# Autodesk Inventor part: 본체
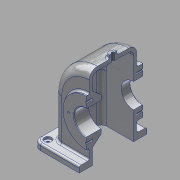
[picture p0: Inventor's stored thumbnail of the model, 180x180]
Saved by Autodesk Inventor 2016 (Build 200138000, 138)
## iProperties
Created: 2018-08
Part Number: 본체
Material: 알루미늄 6061
Document SubType Name: Modeling
Designer: 301-08
Density: 2.7 g/cm^3
Appearance: 알루미늄 - 평지
Mass: 1092.08 g
Surface Area: 1182.21 cm^2
Volume: 404.475 cm^3
Author: 301-08
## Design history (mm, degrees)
sketch "스케치1"
  geometry: L1 (58, 78)-(58, 0); L2 (-58, 78)-(-58, 0); L3 (58, 0)-(-58, 0); A1 r 58 centre (0, 78) between (58, 78) and (-58, 78); 1 further point
  constraints: 6 end point, 2 point on circle, 2 tangent, 2 vertical, 1 centre point, 1 horizontal, 1 midpoint, 1 vertical alignment
  dimensions: "d3" = 58 radius of A1; "d4" = 78 distance from line of L3 A1.centre
extrude "돌출1" new body sketch "스케치1" stored distance "d5" = 77; taper "d6" = 0 deg
sketch "스케치2"
  geometry: L1 (58, 0)-(58, 78) reference; L2 (-58, 78)-(-58, 0) reference; L3 (-52, 0)-(-52, 78); L4 (52, 78)-(52, 0); L5 (52, 0)-(-52, 0); A1 r 58 centre (0, 78) between (58, 78) and (-58, 78) reference; A2 r 52 centre (0, 78) between (52, 78) and (-52, 78); 1 further point
  constraints: 6 end point, 2 point on circle, 2 point on line, 1 centre point, 1 midpoint, 1 perpendicular, 2 other
  dimensions: "d7" = 6 radial gap between concentric circles of A1 A2
extrude "돌출2" cut sketch "스케치2" stored distance "d8" = 67; taper "d9" = 0 deg
sketch "스케치3"
  geometry: L1 (-90.651, 65)-(98.401, 65); C1 r 38 at (0, 65); 1 further point
  constraints: 2 end point, 1 centre point, 1 horizontal, 1 point on line, 1 vertical alignment
  dimensions: "d10" = 65 distance from line of point (0, 0) L1; "d11" = 76 diameter of C1
extrude "돌출3" join sketch "스케치3" distance "d12" = 5; taper "d13" = 0 deg
sketch "스케치4"
  geometry: L1 (81.18, -65)-(-117.972, -65); L2 (58, 0)-(-58, 0) reference; C1 r 38 at (0, -65); 2 further points
  constraints: 2 end point, 1 centre point, 1 horizontal, 1 midpoint, 1 point on line, 1 vertical alignment
  dimensions: "d14" = 65 distance between parallel lines of L2 L1; "d15" = 76 diameter of C1
extrude "돌출4" join sketch "스케치4" distance "d16" = 10; taper "d17" = 0 deg
sketch "스케치5"
  geometry: L1 (-52.99, 65)-(78.307, 65); L2 (33.5, 0)-(-33.5, 0) reference; L3 (-33.5, 130)-(-33.5, 78) reference; L4 (-33.5, 104.747)-(-19.5, 93); L5 (-19.5, 93)-(-19.5, 65); L6 (-33.5, 104.747)-(-33.5, 65); L7 (-33.5, 78)-(-33.5, 0) reference; L8 (-43.5, 103)-(-43.5, 27) reference; 1 further point
  constraints: 8 end point, 4 point on line, 1 horizontal, 1 vertical
  dimensions: "d18" = 65 distance between parallel lines of L2 L1; "d19" = 50 deg angle of L4 L5; "d20" = 56 diameter of L4.end L1; "d21" = 24 distance between parallel lines of L8 L5
revolve "회전1" sketch "스케치5" stored, may be unused: angle "d22" = 90 deg
sketch "스케치6"
  geometry: L1 (133, -93.5)-(-17, -93.5); L2 (-17, -93.5)-(-17, 16.5); L3 (-17, 16.5)-(133, 16.5); L4 (133, 16.5)-(133, -93.5); L5 (133, -93.5)-(-17, 16.5); L6 (-17, -93.5)-(133, 16.5); 1 further point
  constraints: 12 end point, 2 midpoint, 2 parallel, 1 horizontal, 1 perpendicular
  dimensions: "d23" = 150 distance of L2.end L3.end; "d24" = 110 distance of L1.end L2.end
extrude "돌출5" join sketch "스케치6" distance "d25" = 10; taper "d26" = 0 deg
sketch "스케치7"
  geometry: L1 (23, 21.5)-(127, 21.5) reference; L2 (127, 21.5)-(127, 88.5) reference; L3 (23, 88.5)-(23, 21.5) reference; L4 (127, 88.5)-(23, 88.5) reference; L5 (127, 21.5)-(23, 21.5); L6 (23, 21.5)-(127, 21.5) reference; L7 (23, 88.5)-(23, 21.5) reference; L8 (23, 21.5)-(23, 88.5); L9 (127, 21.5)-(127, 88.5); L10 (127, 88.5)-(23, 88.5) reference; L11 (127, 88.5)-(23, 88.5); 1 further point
  constraints: 8 end point, 4 collinear
extrude "돌출6" cut sketch "스케치7" distance "d27" = 10; taper "d28" = 0 deg
sketch "스케치8"
  geometry: L1 (-88.097, 0)-(105.07, 0); C1 r 20 at (0, 0); 1 further point
  constraints: 2 end point, 1 centre point, 1 horizontal, 1 point on line, 1 vertical alignment
  dimensions: "d29" = 65 distance from line of point (0, -65) L1; "d30" = 40 diameter of C1
extrude "돌출7" cut sketch "스케치8" distance "d31" = 24; taper "d32" = 0 deg
sketch "스케치9"
  geometry: L1 (82.709, 0)-(-104.261, 0); L2 (75, 65)-(-75, 65) reference; C1 r 20 at (0, 0); 2 further points
  constraints: 2 end point, 1 centre point, 1 horizontal, 1 midpoint, 1 point on line, 1 vertical alignment
  dimensions: "d33" = 65 distance between parallel lines of L2 L1; "d34" = 40 diameter of C1
extrude "돌출8" cut sketch "스케치9" distance "d35" = 15; taper "d36" = 0 deg
node "작업 평면1"
sketch "스케치10"
  geometry: C1 r 6 at (0, 0); 1 further point
  constraints: 1 centre point, 1 coincident
  dimensions: "d38" = 12 diameter of C1
extrude "돌출9" join sketch "스케치10" stored distance "d39" = 10; taper "d40" = 5 deg
hole "구멍1" diameter "d43" = 4.459; stored, may be unused: countersink angle "d47" = 90 deg, drill point angle "d49" = 118 deg; dims "d41" = 10, "d42" = 10, "d44" = 10, "d45" = 4, "d46" = 2, "d48" = 30.55
fillet "모깎기1" dims "d50" = 12
fillet "모깎기2" dims "d51" = 3
sketch "스케치11"
  geometry: L1 (5, 13.5)-(-121, 13.5) reference; L2 (-130, 4.5)-(-130, -81.5) reference; L3 (-121, -90.5)-(5, -90.5) reference; L4 (14, -81.5)-(14, 4.5) reference; L5 (-116, 0)-(0, 0) reference; L6 (0, 0)-(0, -77) reference; L7 (0, -77)-(-116, -77) reference; L8 (-116, -77)-(-116, 0) reference; L9 (-110, -5)-(-110, -72) reference; L10 (-110, -72)-(-6, -72) reference; L11 (-6, -72)-(-6, -5) reference; L12 (-6, -5)-(-110, -5) reference; A1 r 9 centre (5, 4.5) between (14, 4.5) and (5, 13.5) reference; A2 r 9 centre (-121, 4.5) between (-121, 13.5) and (-130, 4.5) reference; A3 r 9 centre (-121, -81.5) between (-130, -81.5) and (-121, -90.5) reference; A4 r 9 centre (5, -81.5) between (5, -90.5) and (14, -81.5) reference; 5 further points
  constraints: 4 coincident
hole "구멍2" sketch "스케치11" at (-121, 4.5), (-121, -81.5), (5, 4.5), (5, -81.5) diameter "d52" = 5; stored, may be unused: countersink angle "d56" = 90 deg, drill point angle "d58" = 118 deg; dims "d53" = 10, "d54" = 12, "d55" = 4, "d57" = 30.55
fillet "모깎기3" dims "d59" = 13
fillet "모깎기4" dims "d60" = 8
fillet "모깎기5" dims "d61" = 3
fillet "모깎기6" dims "d62" = 3
fillet "모깎기7" dims "d63" = 3
fillet "모깎기8" dims "d64" = 3
sketch "스케치12" dims "d65" = 58
  geometry: C1 r 20 at (0, 0) reference; 3 further points
  constraints: 2 vertical alignment, 1 coincident, 2 other
hole "구멍3" sketch "스케치12" at (0, 29) diameter "d66" = 3.242; stored, may be unused: countersink angle "d70" = 90 deg, drill point angle "d72" = 118 deg; dims "d67" = 8, "d68" = 4, "d69" = 2, "d71" = 10
sketch "스케치13" dims "d76" = 58
  geometry: C1 r 20 at (0, 0) reference; 3 further points
  constraints: 2 vertical alignment, 1 coincident, 2 other
hole "구멍4" sketch "스케치13" at (0, -29) diameter "d77" = 3.242; stored, may be unused: countersink angle "d81" = 90 deg, drill point angle "d83" = 118 deg; dims "d78" = 8, "d79" = 4, "d80" = 2, "d82" = 10
sketch "스케치14"
  geometry: L1 (0, -13)-(65, -13) reference; L2 (78, -17.5)-(78, 68.5) reference; 2 further points
  constraints: 1 other
  dimensions: "d87" = 38.5 distance from line of L1 point (38, 25.5); "d88" = 40 distance from line of L2 point (38, 25.5)
feature "엠보싱1" sketch "스케치14" dims "d3" = 58, "d4" = 78, "d89" = 0.5, "d90" = 0
chamfer "모따기1" distance "d91" = 1; stored, may be unused: second distance "d92" = 2, angle "d93" = 45 deg
sketch "스케치15"
  geometry: L1 (-127.774, 175.34)-(126.375, 175.34); L2 (126.375, 175.34)-(126.375, -54.56); L3 (126.375, -54.56)-(-127.774, -54.56); L4 (-127.774, -54.56)-(-127.774, 175.34); 1 further point
  constraints: 8 end point, 2 parallel, 1 horizontal, 1 perpendicular
extrude "돌출10" cut sketch "스케치15" stored distance "d94" = 10; taper "d95" = 0 deg
node "솔리드1"
pattern_circular "원형 패턴1" dims angle "d74" = 360 deg
pattern_circular "원형 패턴2" dims angle "d85" = 360 deg
node "절단 모서리 투영1"
other parameters: "d37" = 142
